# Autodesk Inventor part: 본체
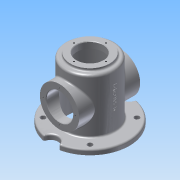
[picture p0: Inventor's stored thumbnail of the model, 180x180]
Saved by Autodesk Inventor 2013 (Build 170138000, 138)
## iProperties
Created: 2018-04
Part Number: 본체
Material: 알루미늄 6061
Document SubType Name: Modeling
Designer: Administrator
Density: 2.71 g/cm^3
Mass: 1501.62 g
Surface Area: 1176.76 cm^2
Volume: 554.102 cm^3
Author: Administrator
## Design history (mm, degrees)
sketch "스케치1"
  geometry: C1 r 80 at (0, 0); 1 further point
  constraints: 1 centre point, 1 coincident
  dimensions: "d0" = 160 diameter of C1
extrude "돌출1" new body sketch "스케치1" distance "d1" = 10; taper "d2" = 0 deg
sketch "스케치2"
  geometry: C1 r 80 at (0, 0) reference; C2 r 50 at (0, 0)
  constraints: 1 centre point, 1 coincident
  dimensions: "d3" = 100 diameter of C2
extrude "돌출2" join sketch "스케치2" distance "d4" = 110; taper "d5" = 0 deg
feature "쉘1" dims "d6" = 10
node "작업 평면3"
sketch "스케치8"
  geometry: C1 r 40 at (0, 0); 1 further point
  constraints: 1 centre point, 1 coincident
  dimensions: "d59" = 80 diameter of C1
extrude "돌출7" join sketch "스케치8" stored distance "d60" = 12; taper "d61" = 0 deg
hole "구멍4" diameter "d64" = 54; stored, may be unused: countersink angle "d68" = 90 deg, drill point angle "d70" = 0 deg; dims "d65" = 8, "d66" = 65, "d67" = 13, "d69" = 13, "d95" = 10, "d96" = 10
sketch "스케치4"
  geometry: C1 r 40 at (0, 0) reference; C2 r 80 at (0, 0) reference; C3 r 50 at (0, 0)
  constraints: 1 centre point, 1 coincident
  dimensions: "d19" = 100 diameter of C3
extrude "돌출4" join sketch "스케치4" distance "d20" = 8; taper "d21" = 0 deg
sketch "스케치5" dims "d22" = 135
  geometry: L1 (0, 0)-(47.73, 47.73); L2 (0, 0)-(67.5, 0); L3 (0, 0)-(-47.73, 47.73); L4 (0, 0)-(-47.73, -47.73); L5 (0, 0)-(47.73, -47.73); C1 r 50 at (0, 0) reference; C2 r 5 at (47.73, 47.73); C3 r 5 at (-47.73, 47.73); C4 r 5 at (-47.73, -47.73); C5 r 5 at (47.73, -47.73); C6 r 15 at (0, -80); C7 r 15 at (0, 80); A1 r 80 centre (0, 0) between (0, -80) and (0, 80) reference; 1 further point
  constraints: 10 end point, 6 centre point, 2 coincident, 2 point on circle, 2 vertical alignment, 1 equal length, 1 horizontal, 20 other
  dimensions: "d27" = 10 diameter of C2; "d28" = 45 deg angle of L2 L1; "d31" = 360 deg dimension on C1.centre L1.end (derived); "d92" = 30 diameter of C6; "d93" = 30 diameter of C7
extrude "돌출5" cut sketch "스케치5" stored distance "d25" = 8; taper "d26" = 0 deg
node "작업 평면2"
  node "작업 평면1"
sketch "스케치6"
  geometry: C1 r 40 at (0, 50); 1 further point
  constraints: 1 centre point, 1 vertical alignment
  dimensions: "d34" = 80 diameter of C1; "d35" = 60 distance of point (0, -10) C1.centre
extrude "돌출6" join sketch "스케치6" stored distance "d36" = 12; taper "d37" = 0 deg
hole "구멍2" diameter "d40" = 54; stored, may be unused: countersink angle "d44" = 90 deg, drill point angle "d46" = 118 deg; dims "d38" = 10, "d39" = 10, "d41" = 6, "d42" = 65, "d43" = 13, "d45" = 8
sketch "스케치7" dims "d47" = 65
  geometry: C1 r 27 at (0, 0) reference; C2 r 40 at (0, 0) reference; 3 further points
  constraints: 2 vertical alignment, 1 coincident, 2 other
hole "구멍3" sketch "스케치7" at (0, 32.5) diameter "d48" = 3.242; stored, may be unused: countersink angle "d52" = 90 deg, drill point angle "d54" = 118 deg; dims "d49" = 8, "d50" = 65, "d51" = 13, "d53" = 10
sketch "스케치9" dims "d71" = 65
  geometry: C1 r 27 at (0, 0) reference; C2 r 40 at (0, 0) reference; 2 further points
  constraints: 2 vertical alignment, 1 coincident, 2 other
hole "구멍5" sketch "스케치9" at (0, 32.5) diameter "d72" = 3.242; stored, may be unused: countersink angle "d76" = 90 deg, drill point angle "d78" = 118 deg; dims "d73" = 8, "d74" = 65, "d75" = 13, "d77" = 10
fillet "모깎기1" dims "d84" = 3
fillet "모깎기2" dims "d85" = 5
chamfer "모따기1" distance "d86" = 1; stored, may be unused: second distance "d87" = 2, angle "d88" = 45 deg
node "작업 평면4"
sketch "스케치10"
  geometry: 2 further points
  constraints: 1 vertical alignment, 1 other
  dimensions: "d89" = 70 distance of point (0, -10) point (0, 60)
feature "엠보싱1" sketch "스케치10" dims "d90" = 0.5, "d91" = 0
hole "구멍6" diameter "d99" = 90; stored, may be unused: countersink angle "d103" = 90 deg, drill point angle "d105" = 118 deg; dims "d97" = 10, "d98" = 10, "d100" = 8, "d101" = 65, "d102" = 13, "d104" = 120
fillet "모깎기3" dims "d106" = 3
node "솔리드1"
mirror "대칭1"
pattern_circular "원형 패턴1" dims angle "d56" = 360 deg
mirror "대칭2"
pattern_circular "원형 패턴2" dims angle "d80" = 360 deg
other parameters: "d33" = 12, "d58" = 5
